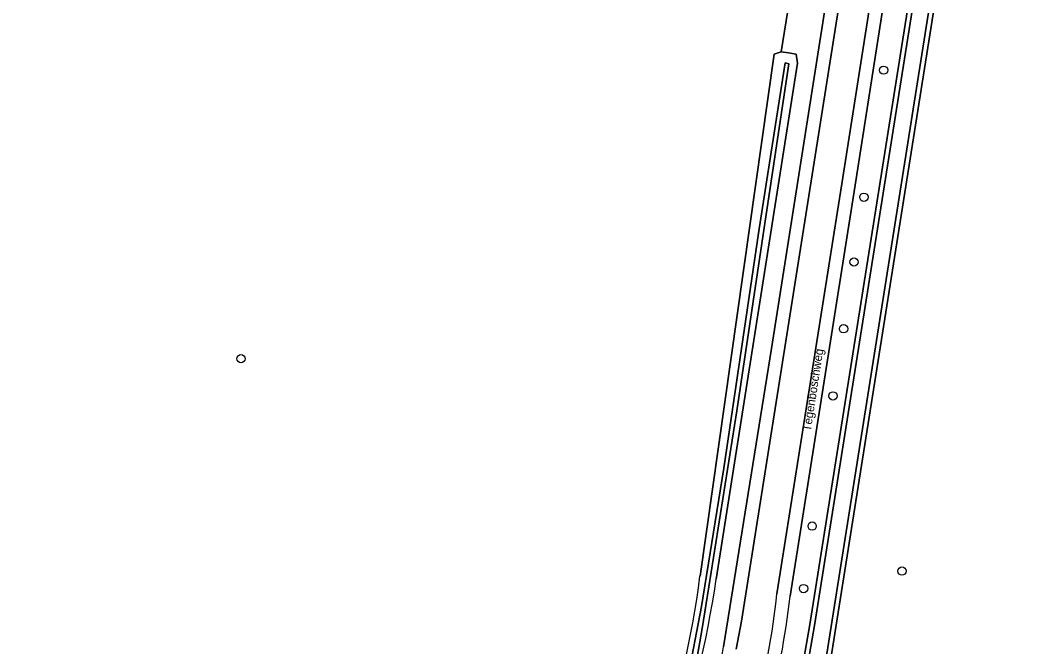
# Model space of a CAD drawing. Extents: x 156502 to 159075, y 384229 to 386100.
# Drawn here: x 156932.1 to 157051.2, y 385635.1 to 385708.8 of the extents above; entities that cross this region are included whole.
import ezdxf

# ---------------------------------------------------------------- set-up
doc = ezdxf.new("R2010")
doc.units = 0
for name, color, linetype in [('IMGEO_Berm_halfverhard', 7, 'Continuous'), ('IMGEO_Boom', 7, 'Continuous'), ('IMGEO_Grasland_agrarisch', 7, 'Continuous'), ('IMGEO_Groenvoorziening', 7, 'Continuous'), ('IMGEO_Oever', 7, 'Continuous'), ('IMGEO_Openbare_ruimte_label', 7, 'Continuous'), ('IMGEO_Rijbaan_lokaal_gesloten', 7, 'Continuous'), ('IMGEO_Waterloop', 7, 'Continuous')]:
    doc.layers.add(name, color=color, linetype=linetype)

msp = doc.modelspace()

# ---------------------------------------------------------------- linework, layer by layer
at = {"layer": 'IMGEO_Berm_halfverhard'}
for points in [[(157035.62, 385733.25), (157028.79, 385689.54), (157021.14, 385641.29)], [(157030.35, 385689.37), (157037.17, 385733.03)], [(157029.08, 385724.73), (157020.51, 385670.14), (157014.85, 385635.05)], [(157016.35, 385634.76), (157016.98, 385638.05), (157029.36, 385716.4)], [(157022.68, 385641.01), (157030.35, 385689.37)]]:
    msp.add_lwpolyline(points, dxfattribs=at)
for centre, radius, start, end in [((156929.43, 385651.03), 92.22, 336.2573, 353.9398), ((156926.45, 385651.78), 96.83, 336.5169, 353.6105), ((156923.22, 385650.8), 92.97, 343.0244, 350.2463)]:
    msp.add_arc(centre, radius, start, end, dxfattribs=at)
at = {"layer": 'IMGEO_Boom'}
for centre in [(157033.69, 385702.9), (157031.37, 385687.95), (157030.2, 385680.33), (157028.97, 385672.47), (156958.04, 385668.95), (157027.73, 385664.57), (157025.28, 385649.25), (157035.85, 385643.95), (157024.27, 385641.9)]:
    msp.add_circle(centre, 0.489, dxfattribs=at)
at = {"layer": 'IMGEO_Grasland_agrarisch'}
for points in [[(157012.08, 385643.36), (157020.79, 385704.78), (157021.65, 385705.04), (157022.63, 385711.17), (157023.38, 385715.75), (156932.05, 385754.59)], [(157128.6, 385670.7), (157041.36, 385721.17), (157027.05, 385630.91), (157026.05, 385625.42)]]:
    msp.add_lwpolyline(points, dxfattribs=at)
msp.add_arc((156908.23, 385656.63), 104.69, 340.5183, 352.716, dxfattribs=at)
at = {"layer": 'IMGEO_Groenvoorziening'}
for points in [[(157023.88, 385631.14), (157025.01, 385637.66), (157038.5, 385722.64), (157038.85, 385724.87), (157040.01, 385732.18), (157042.39, 385766.55)], [(157037.17, 385733.03), (157030.35, 385689.37), (157022.68, 385641.01)], [(157014.85, 385635.05), (157020.51, 385670.14), (157029.08, 385724.73)], [(157026.07, 385719.27), (157024.64, 385710.82), (157023.59, 385711.01), (157022.63, 385711.17), (157021.65, 385705.04), (157022.49, 385704.92), (157023.39, 385704.8), (157023.57, 385703.71), (157013.98, 385643.01)]]:
    msp.add_lwpolyline(points, dxfattribs=at)
for centre, radius, start, end in [((156895.9, 385660.18), 119.32, 340.8403, 351.7245), ((156926.45, 385651.78), 96.83, 336.5169, 353.6105), ((156923.22, 385650.8), 92.97, 343.0244, 350.2463)]:
    msp.add_arc(centre, radius, start, end, dxfattribs=at)
at = {"layer": 'IMGEO_Oever'}
for points in [[(157041.36, 385721.17), (157040.42, 385721.65), (157039.31, 385722.22), (157038.5, 385722.64), (157025.01, 385637.66), (157023.88, 385631.14)], [(157026.05, 385625.42), (157027.05, 385630.91), (157041.36, 385721.17)], [(157021.65, 385705.04), (157020.79, 385704.78), (157012.08, 385643.36)], [(157013.98, 385643.01), (157023.57, 385703.71), (157023.39, 385704.8), (157022.49, 385704.92), (157021.65, 385705.04)], [(157010.56, 385631.01), (157012.25, 385639.8), (157014.87, 385656.07), (157019.03, 385684.21), (157022.12, 385703.75), (157022.52, 385703.66), (157019.86, 385685.9), (157016.4, 385662.83), (157013.1, 385642.1), (157012.33, 385637.2), (157011.73, 385633.84)]]:
    msp.add_lwpolyline(points, dxfattribs=at)
msp.add_lwpolyline([(157040.74, 385720.86), (157026.5, 385631.01), (157025.5, 385625.54), (157023.43, 385618.9), (157020.73, 385612.48), (157017.43, 385606.35), (157013.57, 385600.57), (157003.9, 385586.96), (157002.01, 385584.43), (157000.3, 385585.6), (157002.02, 385588.24), (157006.9, 385594.49), (157011.06, 385599.91), (157014.75, 385605.64), (157017.96, 385611.67), (157020.65, 385617.94), (157022.81, 385624.41), (157024.43, 385631.04), (157025.56, 385637.57), (157038.93, 385721.79)], close=True, dxfattribs=at)
for centre, radius, start, end in [((156908.23, 385656.63), 104.69, 340.5183, 352.716), ((156895.9, 385660.18), 119.32, 340.8403, 351.7245)]:
    msp.add_arc(centre, radius, start, end, dxfattribs=at)
at = {"layer": 'IMGEO_Rijbaan_lokaal_gesloten'}
for points in [[(157021.14, 385641.29), (157028.79, 385689.54), (157035.62, 385733.25)], [(157029.36, 385716.4), (157016.98, 385638.05), (157016.35, 385634.76)]]:
    msp.add_lwpolyline(points, dxfattribs=at)
msp.add_arc((156929.43, 385651.03), 92.22, 336.2573, 353.9398, dxfattribs=at)
at = {"layer": 'IMGEO_Waterloop'}
msp.add_lwpolyline([(157040.74, 385720.86), (157038.93, 385721.79), (157025.56, 385637.57), (157024.43, 385631.04), (157022.81, 385624.41), (157020.65, 385617.94), (157017.96, 385611.67), (157014.75, 385605.64), (157011.06, 385599.91), (157006.9, 385594.49), (157002.02, 385588.24), (157000.3, 385585.6), (157002.01, 385584.43), (157003.9, 385586.96), (157013.57, 385600.57), (157017.43, 385606.35), (157020.73, 385612.48), (157023.43, 385618.9), (157025.5, 385625.54), (157026.5, 385631.01)], close=True, dxfattribs=at)
msp.add_lwpolyline([(157011.73, 385633.84), (157012.33, 385637.2), (157013.1, 385642.1), (157016.4, 385662.83), (157019.86, 385685.9), (157022.52, 385703.66), (157022.12, 385703.75), (157019.03, 385684.21), (157014.87, 385656.07), (157012.25, 385639.8), (157010.56, 385631.01)], dxfattribs=at)

# ---------------------------------------------------------------- texts
at = {"layer": 'IMGEO_Openbare_ruimte_label'}
msp.add_text('Tegenboschweg', height=1, rotation=81.1972, dxfattribs=at).set_placement((157025.11, 385660.35))

doc.saveas('drawing.dxf')
